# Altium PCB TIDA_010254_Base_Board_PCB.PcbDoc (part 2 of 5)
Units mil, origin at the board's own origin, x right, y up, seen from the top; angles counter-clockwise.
Board outline 3514.38 x 3143.81 mil, 4 copper layers (Top Layer, L2_GND1, L3_PWR1, Bottom Layer), stack 62.715 mil thick; 219 components, 146 nets, 618 pads, 2382 vias.
Unrouted connection lines stored in the file: 2280.
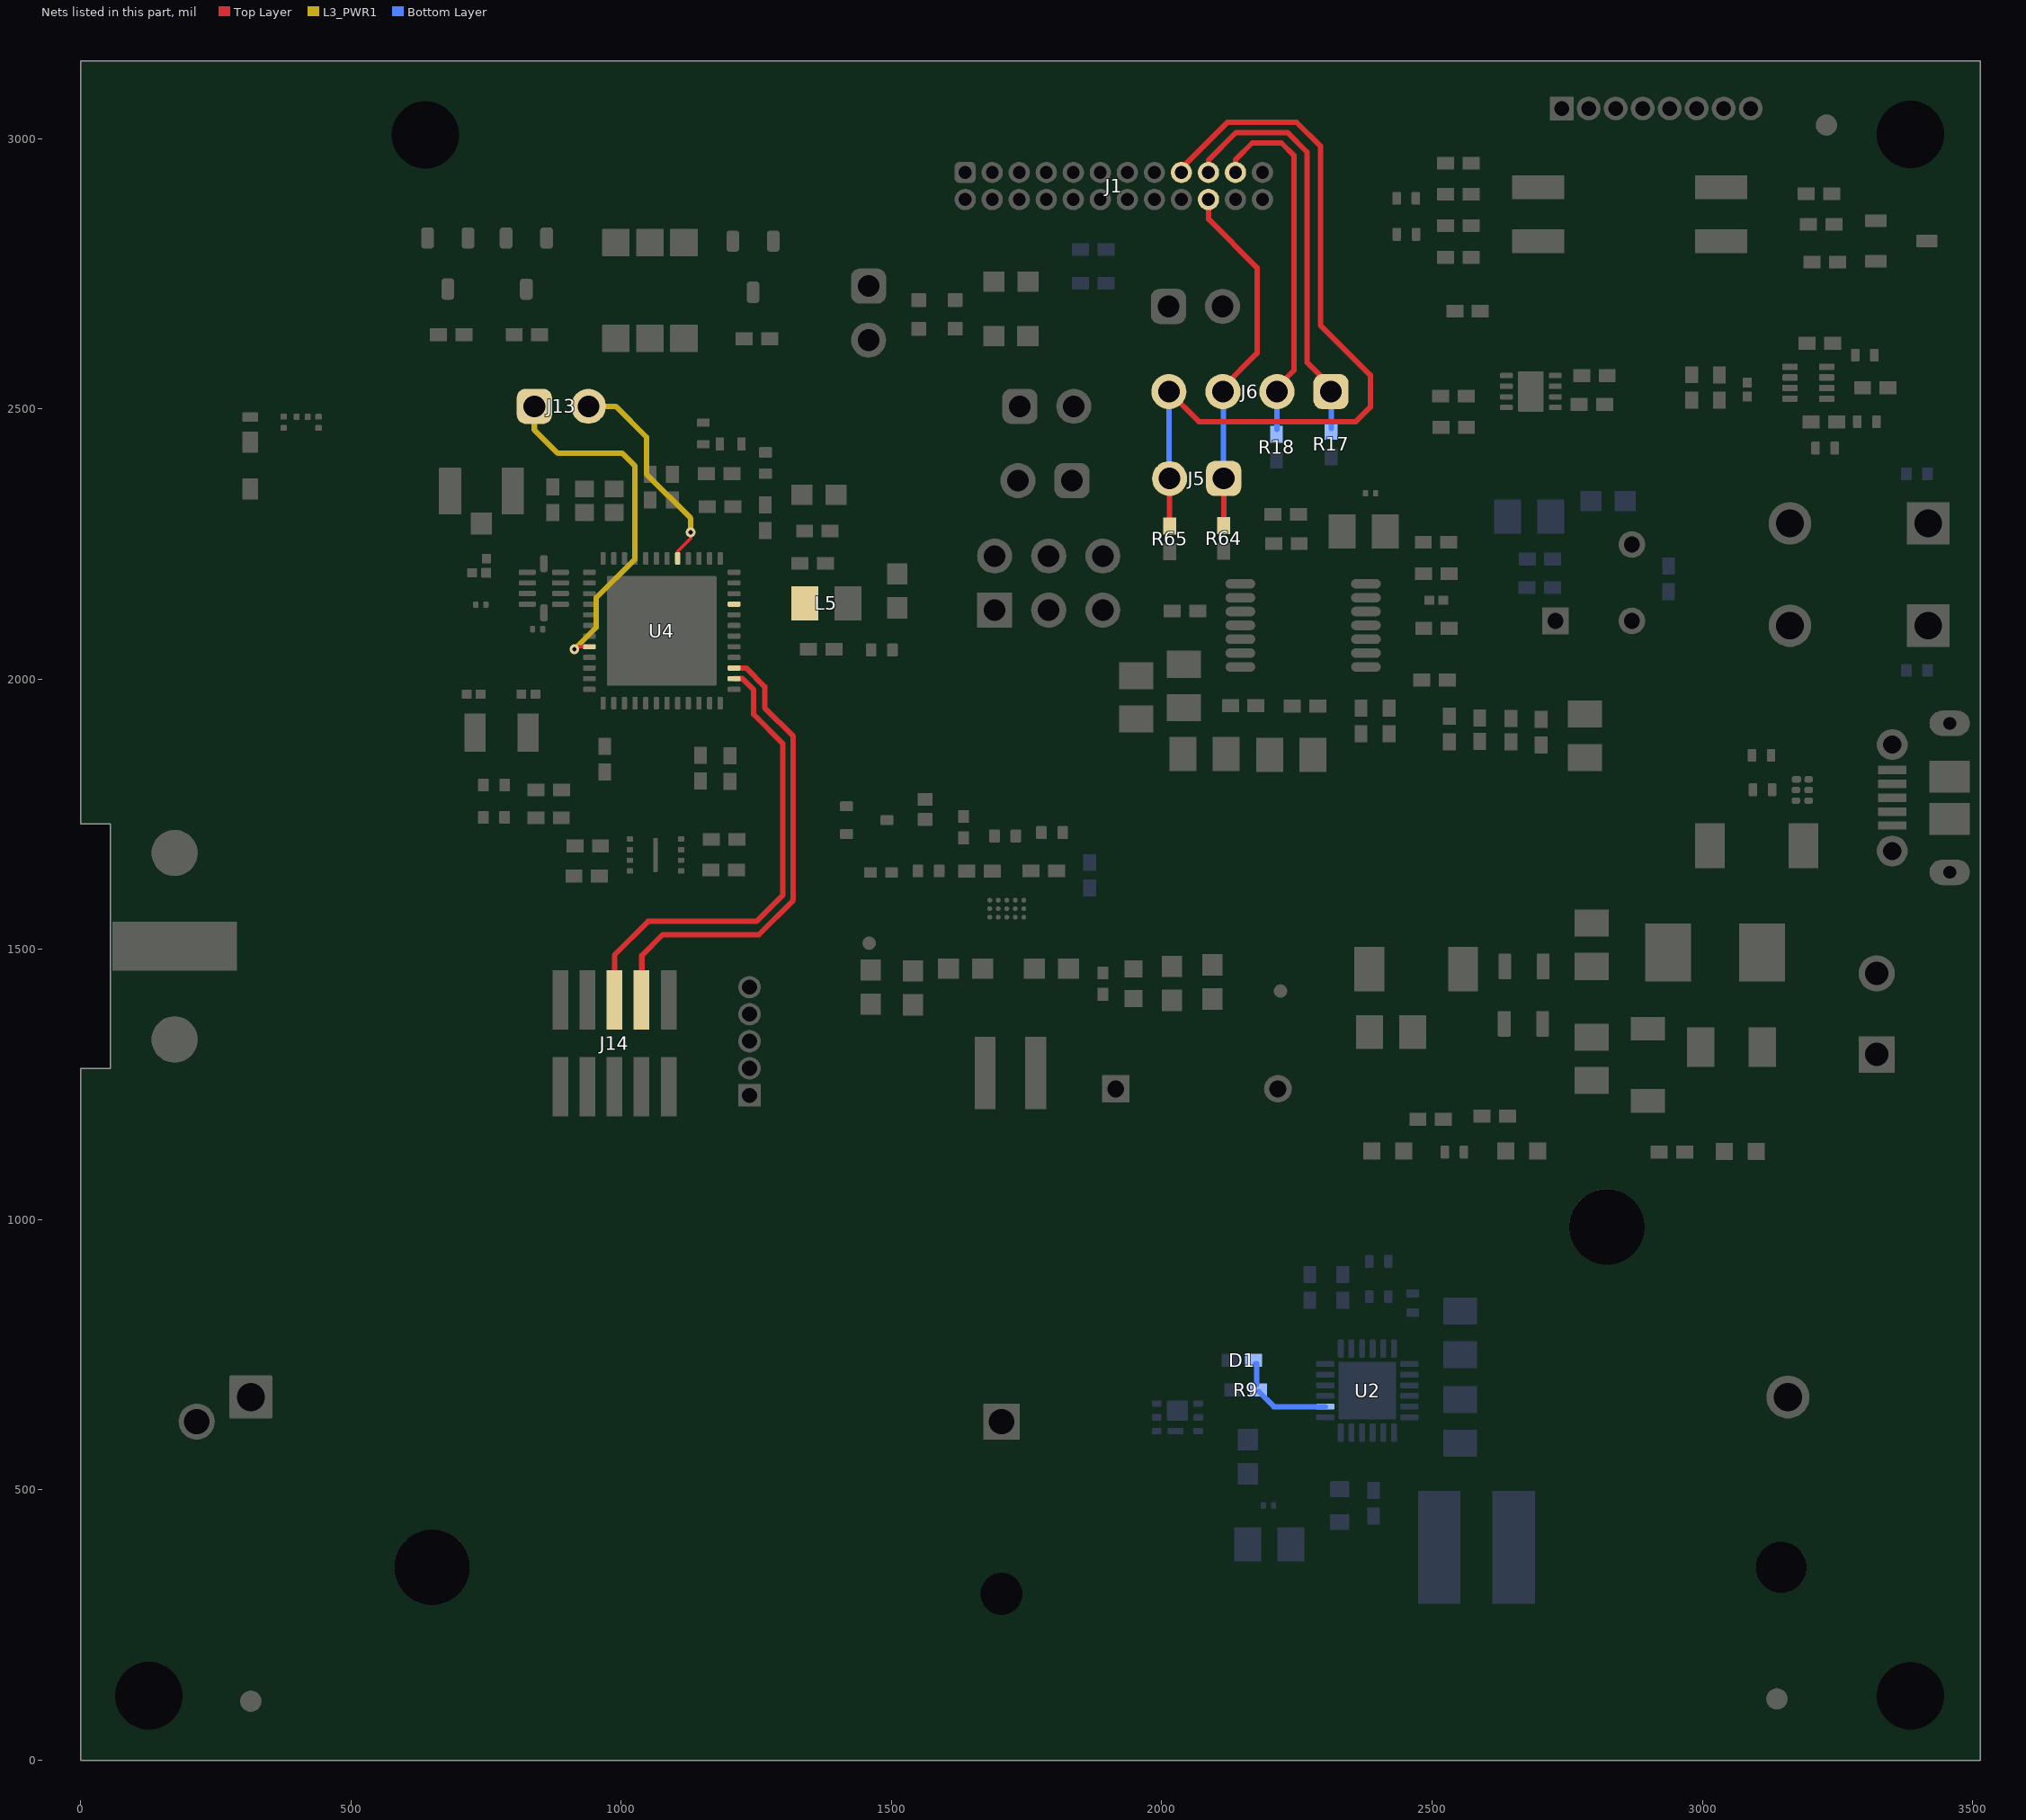
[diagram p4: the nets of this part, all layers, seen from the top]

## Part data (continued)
C26 C27: library part CMP-0088531-2, "0.1µF ±10% 6.3V Ceramic Capacitor X5R 0201 (0603 Metric)", Digikey Part Number=490-3167-1-ND, Manufacturer=Murata, Mouser Part Number=81-GRM033R60J104KE19, Operating Temperature Range="-55°C to +85°C", TempCo=15%, Temperature Characteristic=X5R, Tolerance_%=10%, ValueDisplayed=0.1uF, Voltage=6.3V
C28 C35: library part CMP-0064947-2, "CAP, CERM, 1 uF, 6.3 V,+/- 10%, X7R, 0402", Cap_Case=0402, Manufacturer=MuRata, Supplier Part Number 1=490-10024-1-ND, TempCo=X7R, Tolerance_%=10%, Value1=Unknown, Value2=6.3V, ValueDisplayed=1uF
C29 C31 C36 C37: library part CMP-0009664-3, "CAP, CERM, 12 pF, 50 V, +/- 5%, C0G/NP0, 0201", Cap_Case=0201, Manufacturer=MuRata, Supplier Part Number 1=490-6114-1-ND, TempCo=C0G/NP0, Tolerance_%=5%, Value1=Unknown, Value2=50V, ValueDisplayed=12pF
C30 C33 C34: library part CMP-0086449-1, "Multilayer Ceramic Capacitors MLCC - SMD/SMT 0201 1.2pF 50volts C0G +/-0.1pF", Manufacturer="Murata Electronics North America", PartNumber=GRM0335C1H1R2BA01D, TempCo=30ppm/°C
C42 C58: library part CMP-0009703-2, "CAP, CERM, 0.01 uF, 10 V, +/- 10%, X5R, 0201", Cap_Case=0201, Manufacturer=MuRata, Supplier Part Number 1=490-3166-1-ND, TempCo=X5R, Tolerance_%=10%, Value1=Unknown, Value2=10V, ValueDisplayed=0.01uF
C46: library part CMP-0006674-2, "CAP, CERM, 0.01 uF, 50 V, +/- 10%, X7R, 0402", Cap_Case=0402, Manufacturer=MuRata, Supplier Part Number 1=490-4516-1-ND, TempCo=X7R, Tolerance_%=10%, Value1=Unknown, Value2=50V, ValueDisplayed=0.01uF
C47: library part CMP-0006415-2, "CAP, CERM, 12 pF, 50 V, +/- 5%, C0G/NP0, 0402", Cap_Case=0402, Manufacturer=MuRata, Supplier Part Number 1=14T3292, TempCo=C0G/NP0, Tolerance_%=5%, Value1=Unknown, Value2=50V, ValueDisplayed=12pF
C49 C52: library part CMP-0098152-1, "Chip Multilayer Ceramic Capacitors for General Purpose, 0201, 1000pF, X5R, 15%, 10%, 25V", Manufacturer=Murata, Operating Temperature Range="-55°C to +85°C", TempCo=15%, Temperature Characteristic=X5R, Tolerance_%=10%, ValueDisplayed=1000pF
C51: library part CMP-0007824-2, "CAP, CERM, 33 uF, 10 V, +/- 20%, X5R, 0805", Cap_Case=0805, Manufacturer=TDK, Supplier Part Number 1=445-8238-1-ND, TempCo=X5R, Tolerance_%=20%, Value1="0.001694 ohm", Value2=10V, ValueDisplayed=33uF
C53 C55 C56: library part CMP-0006675-2, "CAP, CERM, 0.1 uF, 50 V, +/- 20%, X7R, 0402", Cap_Case=0402, Manufacturer=MuRata, Supplier Part Number 1=490-10701-1-ND, TempCo=X7R, Tolerance_%=20%, Value1=Unknown, Value2=50V, ValueDisplayed=0.1uF
C54: library part CMP-0006265-2, "CAP, CERM, 3.3 uF, 10 V, +/- 10%, X5R, 0402", Cap_Case=0402, Manufacturer=TDK, Supplier Part Number 1=445-13819-1-ND, TempCo=X5R, Tolerance_%=10%, Value1="0.004157 ohm", Value2=10V, ValueDisplayed=3.3uF
D1: library part CMP-0028378-3, "Diode, Schottky, 40 V, 0.38 A, SOD-523", Manufacturer="Diodes Inc.", Value1=0.38A, Value2=0.79V
D2 D5 D6: library part CMP-0002827-3, "LED, Green, SMD", Color=green, Manufacturer=Lite-On, Power_TotalModule=100mW, Value1=0.1W, Value2=2.1V
D4 D10: library part CMP-0078758-2, "Diode, Schottky, 30 V, 2 A, AEC-Q101, SOD-128", Manufacturer=Nexperia, Value1=2A, Value2=0.36V
D7: library part CMP-0090807-1, "LED Uni-Color Yellow 588nm 2-Pin Chip 0402(1006Metric) T/R", Color=Yellow, Digikey Part Number=VLMY1500-GS08CT-ND, Forward Current=20mA, Manufacturer=Vishay, Mouser Part Number=78-VLMY1500-GS08, Operating Temperature Range="-30°C to +85 °C", Power_TotalModule=75mW
D8: library part CMP-0085925-1, "LED, RGB, SMD", Color=RGB, Manufacturer=Lite-On, Power_TotalModule=130mW, Value1=0.13W, Value2=3.8V
D9: library part CMP-0078243-3, "Diode, TVS, Uni, 5.8 V, 10.5 Vc, AEC-Q101, SMB", Manufacturer=Littelfuse, Value1=0.55W
D11 D12: library part CMP-0076957-3, "Diode, Switching, 75 V, 0.3 A, SOD-523", Manufacturer="Micro Commercial Components", Value1=0.3A, Value2=1.25V
F1: library part CMP-0003458-2, "Fuse, 5 A, 32VAC/VDC, SMD", Irating_A=5A, Manufacturer=Littelfuse, PartNumber=0440005.WR, Supplier Part Number 1=F1608CT-ND
FB1 FB2: library part CMP-0098084-1, "Chip Ferrite Bead, 0805, 30Ω @ 100MHz, 0.014Ω, , 4A", Impedance At Frequency="30Ω @ 100MHz", Manufacturer=Murata, Operating Temperature Range="-55°C to +125°C", Test Frequency=100MHz
FB3 FB4: library part CMP-0089995-1, "120 Ohms @ 100MHz 1 Power Line Ferrite Bead 0603 (1608 Metric) 3A 30mOhm", Digikey Part Number=490-5254-1-ND, Impedance At Frequency="120Ω @ 100MHz", Manufacturer=Murata, Mouser Part Number=81-BLM18KG121TN1D, Operating Temperature Range="-55°C to +125°C", Test Frequency=100MHz, Tolerance_%=25%
FID1 FID2 FID3 FID4 FID5 FID6: library part CMP-0077181-1, "Fiducial mark.  There is nothing to buy or mount.", Manufacturer=N/A
FL1: library part CMP-0088981-1, "RF Balun 862MHz ~ 928MHz, 2.4GHz ~ 2.5GHz 50 / 50Ohm 0805 (2012 Metric), 10 PC Pad", Digikey Part Number=712-1760-1-ND, Manufacturer="Johanson Technology", Mouser Part Number=609-0900PC15A0036E, Operating Temperature Range="-40°C to +85°C"
J1: library part CMP-0067662-1, "Receptacle, 1.27mm, 12x2, Gold, TH", Color=Black, Current_A=1A, Manufacturer="Sullins Connector Solutions", Supplier Part Number 1=S9009E-12-ND, Voltage_V=500V
J2: library part CMP-0075406-2, "Header, 100mil, 3x2, Gold, TH", Color=Black, Current_A=6.3A, Manufacturer=Samtec, Supplier Part Number 1=SAM1028-03-ND, Voltage_V=550V
J3 J4 J5 J7 J13 J16: library part CMP-0075405-3, "Header, 100mil, 2x1, Gold, TH", Color=Black, Current_A=6.3A, Manufacturer=Samtec, Supplier Part Number 1=SAM1029-02-ND, Voltage_V=550V
J6: library part CMP-0075409-2, "Header, 100mil, 4x1, Gold, TH", Color=Black, Current_A=6.3A, Manufacturer=Samtec, Supplier Part Number 1=SAM1029-04-ND, Voltage_V=550V
J8: library part CMP-0055472-1, "Conn Term Block, 2POS, 3.81mm, TH", Manufacturer="Phoenix Contact", Supplier Part Number 1=277-1947-ND
J9: library part CMP-0055293-1, "Connector, Receptacle, Micro-USB Type B, R/A, Bottom Mount SMT", Manufacturer=Molex, Supplier Part Number 1=WM1399CT-ND
J10: library part CMP-0087962-2, "SMA Connector Receptacle, Female Socket 50Ohm Board Edge, End Launch Solder", Manufacturer="Molex Inc"
J11: library part CMP-0091846-1, "U.FL (UMCC) Connector Jack, Male Pin 50Ohm Surface Mount Solder", Dielectric Material="Liquid Crystal Polymer", Digikey Part Number=A118077CT-ND, Frequency_Fixed=0-6GHz, Manufacturer="TE Connectivity", Mouser Part Number=571-1909763-1, Operating Temperature Range="-40°C to +90°C"
J12: library part CMP-0092742-1, "8 Position Receptacle Connector 0.050\" (1.27mm) Through Hole Gold", Current_A=3A, Digikey Part Number=851-43-008-10-021000-ND, Manufacturer=Mill-Max, Mouser Part Number=575-8514300810021000, Operating Temperature Range="-55°C to +125°C"
J14: library part CMP-0075670-2, "Header (Shrouded), 1.27mm, 5x2, Gold, SMT", Color=Black, Current_A=3.3A, Manufacturer=Samtec, Supplier Part Number 1=SAM8796-ND
J15: library part CMP-0074998-1, "Receptacle, 5x1, 1.27mm, TH", Manufacturer=Preci-Dip, Supplier Part Number 1=1212-1349-ND
J17: library part CMP-0097895-1, "Battery Holder (Open) 18650 1 Cell PC Pin", Digikey Part Number=36-1043P-ND, Manufacturer=Keystone, Mouser Part Number=534-1043P, Operating Temperature Range="-50°C to +145°C"
L3: library part CMP-0063878-1, "Inductor, Shielded Drum Core, Ferrite, 1 uH, 3.3 A, 0.019 ohm, SMD", Manufacturer="Wurth Elektronik", Supplier Part Number 1=732-3028-1-ND, Value1="0.019 ohm", Value2=3.3A, ValueDisplayed=1uH
L4: library part CMP-0061147-1, "Inductor, Shielded, Composite, 470 nH, 3.5 A, 0.0076 ohm, SMD", Manufacturer=Coilcraft, Supplier Part Number 1=994-XFL4015-471MEC, Value1="0.0076 ohm", Value2=3.5A, ValueDisplayed=470nH
L5: library part CMP-0062727-1, "Inductor, Multilayer, Ferrite, 6.8 uH, 0.11 A, 0.25 ohm, SMD", Manufacturer=TDK, Supplier Part Number 1=445-6761-1-ND, Value1="0.25 ohm", Value2=0.11A, ValueDisplayed=6.8uH
L6: library part CMP-0003349-2, "Ferrite Bead, 1500 ohm @ 100 MHz, 0.5 A, 0603", Manufacturer=MuRata, Supplier Part Number 1=490-5216-1-ND, Value1="0.5 ohm", Value2=0.5A, ValueDisplayed="1500 ohm"
Logo1: library part CMP-0074844-2, Manufacturer="Texas Instruments"
Logo5: library part CMP-0074838-1, "Texas Instrument Corporate Signature"
Logo7: library part CMP-0074847-1, "FCC_disclaimer"
Logo8: library part CMP-0074769-4, Manufacturer="Texas Instruments"
MH1 MH2 MH3 MH4: library part CMP-0078424-2, "PCB Mounting Hole, No Pad", Manufacturer=Any, PartNumber=N/A
Q1: library part CMP-0000585-1, "MOSFET, N-CH, 30 V, 22 A, DQK0006C (WSON-6)", Alternate Manufacturer=None, Manufacturer="Texas Instruments", Supplier Part Number 1=296-37193-1-ND, Value1=0.02, Value2="2.4 nC"
Q5: library part CMP-0000948-2, "MOSFET, N-CH, 100 V, 0.17 A, SOT-323", Alternate Manufacturer=None, Manufacturer="Diodes Inc.", Supplier Part Number 1=BSS123W-FDICT-ND, Value1=1
Q6 Q7 Q8: library part CMP-0000461-2, "Transistor, NPN, 40 V, 0.6 A, SOT-23", Manufacturer="ON Semiconductor", Supplier Part Number 1=MMBT2222ALT1GOSCT-ND, Value1="0.6 A"
R1 R2 R10 R14 R16 R45 R46 R47 R52 R66 R76: library part CMP-0094735-1, "10 kOhms ±1% 0.063W, 1/16W Chip Resistor 0402 (1005 Metric)  Thick Film", Digikey Part Number=541-3959-1-ND, Manufacturer=Vishay, Mouser Part Number=71-CRCW040210K0FKEDC, Operating Temperature Range="-55°C to +155°C", Part Number=CRCW040210K0FKEDC, Power_W=63mW, TempCo=100ppm/°C, Tolerance_%=1%
R3: library part CMP-0022336-4, "RES, 332 k, 1%, 0.1 W, AEC-Q200 Grade 0, 0603", Manufacturer=Vishay-Dale, Power_W=100mW, Supplier Part Number 1=541-332KHCT-ND, TempCo="100 ppm/C", Tolerance_%=1%, Value2=0.1W, Value_Code=332k
R4: library part CMP-0026517-2, "RES, 6.81 k, 1%, 0.063 W, AEC-Q200 Grade 0, 0402", Manufacturer=Vishay-Dale, Power_W=63mW, Supplier Part Number 1=541-6.81KLCT-ND, TempCo="100 ppm/C", Tolerance_%=1%, Value2=0.063W, Value_Code=6k81, ValueDisplayed=6.81k
R5: library part CMP-0026022-3, "RES, 150, 1%, 0.063 W, AEC-Q200 Grade 0, 0402", Manufacturer=Vishay-Dale, Power_W=63mW, Supplier Part Number 1=541-150LCT-ND, TempCo="100 ppm/C", Tolerance_%=1%, Value2=0.063W, Value_Code=150R, ValueDisplayed=150
R6 R8 R55 R61 R62: library part CMP-0020831-2, "RES, 15 M, 5%, 0.125 W, AEC-Q200 Grade 0, 0805", Manufacturer="Stackpole Electronics Inc", Power_W=125mW, Supplier Part Number 1=RMCF0805JT15M0CT-ND, TempCo="200 ppm/C", Tolerance_%=5%, Value2=0.125W, Value_Code=15M0, ValueDisplayed=15M
R7 R12 R15 R27 R28 R29 R35: library part CMP-0026232-2, "RES, 2.21 k, 1%, 0.063 W, AEC-Q200 Grade 0, 0402", Manufacturer=Vishay-Dale, Power_W=63mW, Supplier Part Number 1=541-2.21KLCT-ND, TempCo="100 ppm/C", Tolerance_%=1%, Value2=0.063W, Value_Code=2k21, ValueDisplayed=2.21k
R9 R17 R18 R41 R42 R43 R44 R48 R54 R57 R58 R60 R63 R64 R65 R67 R68 R71 R72 R73 R74: library part CMP-0027004-2, "RES, 0, 5%, 0.063 W, 0402", Manufacturer="Yageo America", Power_W=63mW, Supplier Part Number 1=311-0.0JRCT-ND, TempCo="200 ppm/C", Tolerance_%=5%, Value2=0.063W, Value_Code=0000, ValueDisplayed=0
R11: library part CMP-0026726-1, "RES, 1.50 M, 1%, 0.063 W, 0402", Manufacturer="Yageo America", Power_W=63mW, Supplier Part Number 1=RC0402FR-071M5L-ND, TempCo="100 ppm/C", Tolerance_%=1%, Value2=0.063W, Value_Code=1M50, ValueDisplayed=1.50M
R13: library part CMP-0026680-1, "RES, 220, 1%, 0.1 W, AEC-Q200 Grade 0, 0402", Manufacturer=Panasonic, Power_W=100mW, Supplier Part Number 1=P220LCT-ND, TempCo="100 ppm/C", Tolerance_%=1%, Value2=0.1W, Value_Code=220R, ValueDisplayed=220
R19: library part CMP-0026435-2, "RES, 511 k, 1%, 0.063 W, AEC-Q200 Grade 0, 0402", Manufacturer=Vishay-Dale, Power_W=63mW, Supplier Part Number 1=541-511KLCT-ND, TempCo="100 ppm/C", Tolerance_%=1%, Value2=0.063W, Value_Code=511k
R20: library part CMP-0026158-2, "RES, 200 k, 1%, 0.063 W, AEC-Q200 Grade 0, 0402", Manufacturer=Vishay-Dale, Power_W=63mW, Supplier Part Number 1=541-200KLCT-ND, TempCo="100 ppm/C", Tolerance_%=1%, Value2=0.063W, Value_Code=200k
R21 R26 R31 R33 R37 R49: library part CMP-0094182-1, "100 kOhms ±5% 0.063W, 1/16W Chip Resistor 0402 (1005 Metric) Moisture Resistant Thick Film", Digikey Part Number=311-100KJRCT-ND, Manufacturer=YAGEO, Mouser Part Number=603-RC0402JR-07100KL, Operating Temperature Range="-55°C to +155°C", Part Number=RC0402JR-07100KL, Power_W=63mW, TempCo=100ppm/°C, Tolerance_%=5%
R22: library part CMP-0080879-1, "RES, 91.0 k, 1%, 0.063 W, 1x0.5mm", Manufacturer="Yageo America", Power_W=63mW, Supplier Part Number 1=311-91.0KLRCT-ND, TempCo="100 ppm/C", Tolerance_%=1%, Value2=0.063W, Value_Code=91k0, ValueDisplayed=91.0k
R23 R24: library part CMP-0078212-1, "RES, 510, 5%, 0.1 W, AEC-Q200 Grade 0, 0402", Manufacturer=Panasonic, Power_W=100mW, Supplier Part Number 1=P510JCT-ND, TempCo="200 ppm/C", Tolerance_%=5%, Value2=0.1W, Value_Code=510R, ValueDisplayed=510
R25 R30 R32: library part CMP-0026938-5, "RES, 4.7 k, 5%, 0.063 W, AEC-Q200 Grade 0, 0402", Manufacturer=Vishay-Dale, Power_W=63mW, Supplier Part Number 1=541-4.7KJCT-ND, TempCo="200 ppm/C", Tolerance_%=5%, Value2=0.063W, Value_Code=4k70, ValueDisplayed=4.7k
R34 R36 R56: library part CMP-0026506-2, "RES, 68.1 k, 1%, 0.063 W, AEC-Q200 Grade 0, 0402", Manufacturer=Vishay-Dale, Power_W=63mW, Supplier Part Number 1=541-68.1KLCT-ND, TempCo="100 ppm/C", Tolerance_%=1%, Value2=0.063W, Value_Code=68k1, ValueDisplayed=68.1k
R38 R50 R51: library part CMP-0026890-5, "RES, 2.2 k, 5%, 0.063 W, AEC-Q200 Grade 0, 0402", Manufacturer=Vishay-Dale, Power_W=63mW, Supplier Part Number 1=541-2.2KJCT-ND, TempCo="200 ppm/C", Tolerance_%=5%, Value2=0.063W, Value_Code=2k20, ValueDisplayed=2.2k
R39 R40: library part CMP-0092287-1, "100 ±5% 0.063W, 1/16W Chip Resistor 0402 (1005 Metric) Moisture Resistant Thick Film", Digikey Part Number=13-RC0402JR-13100RLTR-ND, Manufacturer=Yageo, Mouser Part Number=603-RC0402JR-13100RL, Operating Temperature Range="-55°C to +155°C", Power_W=63mW, TempCo=100ppm/°C, Tolerance_%=5%
R53: library part CMP-0026757-1, "RES, 1.00 M, 1%, 0.063 W, AEC-Q200 Grade 0, 0402", Manufacturer="Stackpole Electronics Inc", Power_W=63mW, Supplier Part Number 1=RMCF0402FT1M00CT-ND, TempCo="100 ppm/C", Tolerance_%=1%, Value2=0.063W, Value_Code=1M00, ValueDisplayed=1.00M
R59: library part CMP-0026111-2, "RES, 1.30 M, 1%, 0.063 W, AEC-Q200 Grade 0, 0402", Manufacturer=Vishay-Dale, Power_W=63mW, Supplier Part Number 1=541-1.30MLCT-ND, TempCo="100 ppm/C", Tolerance_%=1%, Value2=0.063W, Value_Code=1M30, ValueDisplayed=1.30M
R70 R77: library part CMP-0026557-2, "RES, 7.87 k, 1%, 0.063 W, AEC-Q200 Grade 0, 0402", Manufacturer=Vishay-Dale, Power_W=63mW, Supplier Part Number 1=541-7.87KLCT-ND, TempCo="100 ppm/C", Tolerance_%=1%, Value2=0.063W, Value_Code=7k87, ValueDisplayed=7.87k
R75 R78: library part CMP-0026574-2, "RES, 82.5 k, 1%, 0.063 W, AEC-Q200 Grade 0, 0402", Manufacturer=Vishay-Dale, Power_W=63mW, Supplier Part Number 1=541-82.5KLCT-ND, TempCo="100 ppm/C", Tolerance_%=1%, Value2=0.063W, Value_Code=82k5, ValueDisplayed=82.5k
S1 S2: library part CMP-0002133-2, "Switch, Tactile, SPST-NO, 0.05A, 12V, TH", CurrentRating_mA=50A, Manufacturer="C&K Components", Supplier Part Number 1=CKN9102-ND
S3: library part CMP-0002290-1, "Switch, SPST, Slide, Off-On, 2 Pos, 0.1A, 20V, SMD", CurrentRating_mA=100A, Manufacturer="CTS Electrocomponents", Supplier Part Number 1=CT2192MST-ND
SH-J1 SH-J2: library part CMP-0003623-3, "Shunt, 100mil, Gold plated, Black", Alternate Manufacturer=3M, Alternate PartNumber=969102-0000-DA, Manufacturer=Samtec, PartNumber=SNT-100-BK-G, Supplier Part Number 1=SAM8858-ND
SW1: library part CMP-0087382-1, "Dip Switch SPST 1 Position Through Hole Slide (Standard) Actuator 25mA 24VDC", Manufacturer=Wurth
TP1 TP2: library part CMP-0078143-4, "TEST POINT.  No entry in BOM.", Manufacturer=N/A
U1: library part CMP-0043115-3, "4-Channel ESD Protection Array for High-Speed Data Interfaces, DRY0006A (USON-6)", Breakdown Voltage(Min)(V)=6, IO Capacitance(Typ)(pF)=1.6, IO Leakage Current(nA)=1, Manufacturer="Texas Instruments", Operating Temperature Range="-40 to 85 C", Rating=Catalog
U2: library part CMP-0860206-1, "BQ25616JRTW, RTW0024P (PVQFN-24)", Alternate Manufacturer="Texas Instruments"
U3: library part CMP-0086313-1, "2 A, High-Efficient, Low IQ Buck- Boost Converter with Small Solution Size, YFF0015AHAN (DSBGA-15)", Alternate Manufacturer="Texas Instruments"
U4: library part CMP-0081246-4, "SimpleLink High-Performance Dual-Band Wireless MCU, RGZ0048A (VQFN-48)", Alternate Manufacturer="Texas Instruments", Alternate PartNumber=CC1352R1F3RGZT
U5: library part CMP-0086600-1, "Ultra Low Power 8M-BIT [x 1/x 2/x 4] CMOS MXSMIO FLASH MEMORY", Manufacturer="Macronix International Co., Ltd."
U6: library part CMP-0087942-2, "Integrated Humidity and Temperature Digital Sensor", Manufacturer="Texas Instruments", Operating Temperature Range="-45°C to +150°C"
U7: library part CMP-0078026-1, "Ultra-Low Power 1.65V to 5.5V Hall Effect Switch Sensor, DBZ0003A (SOT-23-3)", Alternate Manufacturer="Texas Instruments"
U8: library part CMP-0095235-1, "Ambient Light Sensor (ALS) With Excellent Angular IR Rejection 1.6-3.6V 1.8-3.7mA I2C", Manufacturer="Texas Instruments", Max Supply Voltage=3.6V, Min Supply Voltage=1.6V, Operating Supply Current=1.8-3.7uA, Operating Temperature Range="-40°C to +85°C"
U9: library part CMP-0013616-3, "500 nA RRIO Nanopower Operational Amplifier, PW0014A (TSSOP-14)", Alternate Manufacturer="Texas Instruments", Alternate PartNumber=TLV8544PWT
U10: library part CMP-0080109-2, "Pyro Electric Infrared Sensor Fresnel Lens, TH", Manufacturer=MuRata
Y1: library part CMP-0079303-1, "Crystal, 32.768 KHz, 20 ppm, 7 pF, SMD", Frequency Stability="20 ppm", Frequency_Fixed=32.768kHz, Load Capacitance="7 pF", Manufacturer=Epson, PartNumber="FC-135 32.7680KA-AG0", Supplier Part Number 1=732-FC135-32.76KAAG0
Y2: library part CMP-0081467-1, "Crystal, 48 MHz, 10 ppm, 7 pF, SMD", Frequency Stability="20 ppm", Frequency Tolerance="10 ppm", Frequency_Fixed=48MHz, Load Capacitance="7 pF", Manufacturer=Kyocera, Supplier Part Number 1=581-CX2016DB48CFPLC1
ZZ1: library part CMP-0003616-3
ZZ2: library part CMP-0077236-1
ZZ3: library part CMP-0077237-1
ZZ4 ZZ5: library part CMP-0077238-1

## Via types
v1: diameter 18, hole 8, Top Layer to Bottom Layer, tented both sides, 2351 vias
v2: diameter 19.68, hole 7.87, Top Layer to Bottom Layer, 21 vias
v3: diameter 19.68, hole 11.81, Top Layer to Bottom Layer, 9 vias
v4: diameter 18, hole 8, Top Layer to Bottom Layer, tented bottom, 1 vias

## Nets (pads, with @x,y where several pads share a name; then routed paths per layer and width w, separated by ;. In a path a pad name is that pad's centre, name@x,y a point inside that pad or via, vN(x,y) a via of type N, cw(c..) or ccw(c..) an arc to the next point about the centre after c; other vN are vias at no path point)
ACDRV: D1.1 R9.2 U2.2 | length 174.8
  Bottom Layer w10: D1.1@2173.32,734.02 2174.91,734.02 2175.92,733.01 R9.2@2175.92,695.3 ; R9.2@2179.78,681.85 2207.4,654.23 U2.2@2302.44,654.23
DCA_LP_SPI_CLK_I2C_SCL: J1.20 J5.1 J6.3 R64.1 | length 644
  Top Layer w10: J1.20@2086.76,2888.92 2086.76,2850.82 2176.16,2761.41 2176.16,2602.8 J6.3@2114.03,2540.66 ; J5.1@2114.03,2383.68 J5.1@2115.77,2381.93 ; R64.1@2114.38,2298.45 2114.44,2298.5 J5.1@2114.44,2371.16 J5.1@2114.99,2370.6
  Bottom Layer w10: J5.1@2114.03,2383.68 J6.3@2114.03,2540.66
DCA_LP_SPI_CS_I2C_SDA: J1.17 J5.2 J6.4 R65.1 | length 1494.2
  Top Layer w10: J6.4@2013.01,2531.94 2068.37,2476.57 2359.2,2476.57 2385.82,2503.2 2385.82,2562.42 2293.35,2654.9 2293.35,2986.35 2249.64,3030.06 2121.3,3030.06 2036.28,2945.03 J1.17@2036.28,2937.4 ; R65.1@2014.44,2282.56 J5.2@2014.44,2371.16
  Bottom Layer w10: J5.2@2013.72,2371.87 J6.4@2013.72,2531.22
DCA_LP_SPI_MISO_REG_MODE: J1.19 J6.1 R17.1 | length 762.6
  Top Layer w10: J1.19@2086.28,2937.4 2086.28,2960.13 2137.36,3011.21 2232.55,3011.21 2268.46,2975.3 2268.46,2586.23 J6.1@2314.03,2540.66
  Bottom Layer w10: J6.1@2313.01,2531.94 2313.47,2531.47 R17.1@2313.47,2463.98
DCA_LP_SPI_MOSI: J1.21 J6.2 R18.1 | length 664.6
  Top Layer w10: J1.21@2136.57,2937.69 2136.57,2961.4 2167.17,2991.99 2221.29,2991.99 2244.46,2968.81 2244.46,2571.1 J6.2@2214.03,2540.66
  Bottom Layer w10: R18.1@2213.01,2461.93 J6.2@2213.01,2531.94
DCDC_SW: L5.1 U4.33
DEBUG_RX: J13.1 U4.8 | length 672.1
  Top Layer w6: v1(913.32,2055.48) 916.57,2055.48 921.02,2059.93 U4.8@940.97,2059.93
  L3_PWR1 w10: J13.1@839.29,2504.8 839.29,2461.16 882.66,2417.8 1002.1,2417.8 1025.39,2394.5 1025.39,2222.33 953.68,2150.62 953.68,2095.44 v1@913.72,2055.48
DEBUG_TX: J13.2 U4.41 | length 399.4
  Top Layer w6: U4.41@1104.36,2223.32 1104.36,2236.12 1128.46,2260.23 v1(1128.46,2271.78)
  L3_PWR1 w10: J13.2@939.29,2504.8 989.71,2504.8 1046.5,2448.01 1046.5,2379.58 1128.46,2297.62 v1(1128.46,2271.78)
DIO16_TDO: J14.6 U4.26 | length 896.2
  Top Layer w10: J14.6@987.62,1397.82 987.62,1489.8 1049.66,1551.83 1250.43,1551.83 1299.07,1600.48 1299.07,1880.55 1244.92,1934.71 1244.92,1980.2 1224.24,2000.88 U4.26@1208.69,2000.88
DIO17_TDI: J14.8 U4.27 | length 886
  Top Layer w10: J14.8@1038.09,1413.3 1038.09,1488.67 1076.58,1527.16 1254.5,1527.16 1318.24,1590.89 1318.24,1894.19 1265.44,1946.99 1265.44,1986.13 1231,2020.56 U4.27@1208.69,2020.56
